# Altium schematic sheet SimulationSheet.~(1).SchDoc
size A; SheetNumber: 1; SheetTotal: 1
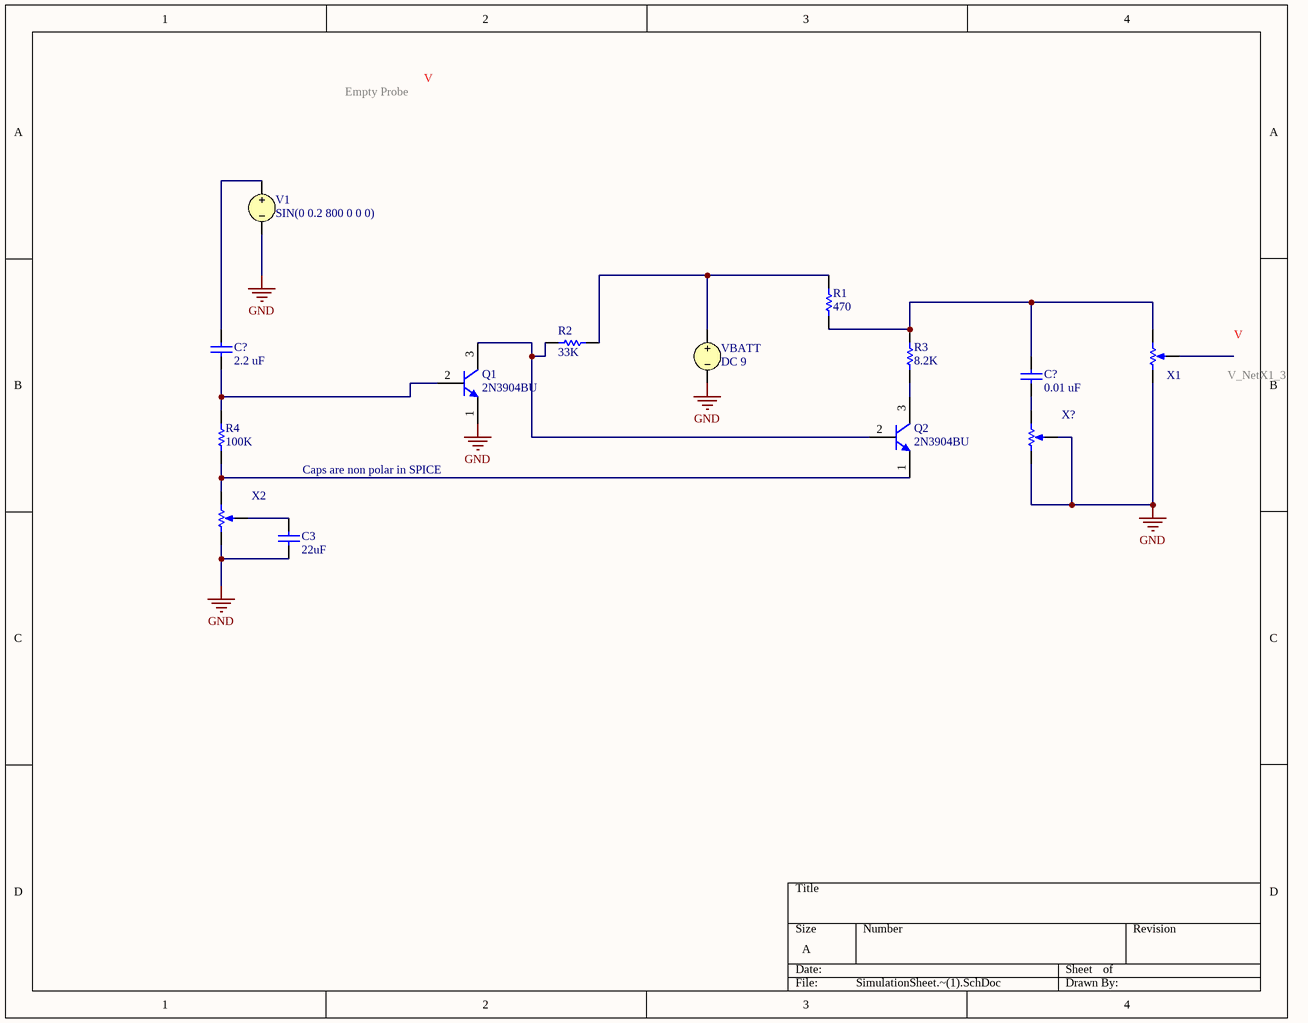
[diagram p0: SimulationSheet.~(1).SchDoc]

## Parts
(Parts that share a designator on the sheet are numbered #1, #2 ... from top to bottom, then left to right.)
C3  value 22uF  (hidden comment: Capacitor)
C?#1  value 2.2 uF  (hidden comment: Capacitor)
C?#2  value 0.01 uF  (hidden comment: Capacitor)
Q1  2N3904BU  [FAIR-TO-92]
Q2  2N3904BU  [FAIR-TO-92]
R1  value 470  (hidden comment: Resistor)
R2  value 33K  (hidden comment: Resistor)
R3  value 8.2K  (hidden comment: Resistor)
R4  value 100K  (hidden comment: Resistor)
V1  SIN(0 0.2 800 0 0 0)
VBATT  DC 9
X1  Potentiometer  (value not drawn)
X2  Potentiometer  (value not drawn)
X?  Potentiometer  (value not drawn)

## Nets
GND: C3.1 Q1.1(E) V1.2 VBATT.2 X1.1(TOP) X2.1(TOP) X?.1(TOP) X?.3(TAP)
NetC3_2: C3.2 X2.3(TAP)
NetC?#1_1: C?#1.1 Q1.2(B) R4.2
NetC?#1_2: C?#1.2 V1.1
NetC?#2_1: C?#2.1 X?.2(BOT)
NetC?#2_2: C?#2.2 R1.1 R3.1 X1.2(BOT)
NetQ1_3: Q1.3(C) Q2.2(B) R2.2
NetQ2_1: Q2.1(E) R4.1 X2.2(BOT)
NetQ2_3: Q2.3(C) R3.2
NetR1_2: R1.2 R2.1 VBATT.1

Not connected (* = marked no-connect by the designer): X1 3(TAP)

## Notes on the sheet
- Caps are non polar in SPICE

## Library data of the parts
C3 C?#1 C?#2 = Capacitor: SimulationGenericComponent: True
Q1 Q2 = CMP-2000-04944-1: NPN General-Purpose Amplifier, 40 V VCEO, 0.2 A, -55 to 150 degC, 2-Pin TO-92, RoHS, Bulk; Manufacturer: FairchildSemiconductor; Maximum Collector Base Voltage: 60V; Minimum DC Current Gain: 40@0.1mA@1V; Maximum Collector Emitter Voltage: 40V; Maximum DC Collector Current: 0.2A; Rad Hard: No; Maximum Operating Frequency: 300(Min)MHz; Maximum Collector Emitter Saturation Voltage: 0.2@1mA@10mA; Maximum Power Dissipation: 625mW
R1-R4 = Resistor: TC1: 0; SimulationGenericComponent: True
V1 = VSRC: Voltage Source; Note: PCB Footprint - Not required; AC Magnitude: 1; AC Phase: 0; Carrier Frequency: 10Meg; Modulation Index: 5; Signal Frequency: 1Meg; Amplitude: 0.2; Frequency: 800
VBATT = VSRC: Voltage Source; Note: PCB Footprint - Not required; AC Magnitude: 1; AC Phase: 0; Value: 9
X1 X? = Potentiometer: value: 500k; position: 0.1; SimulationGenericComponent: True
X2 = Potentiometer: value: 1k; position: 0.2; SimulationGenericComponent: True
